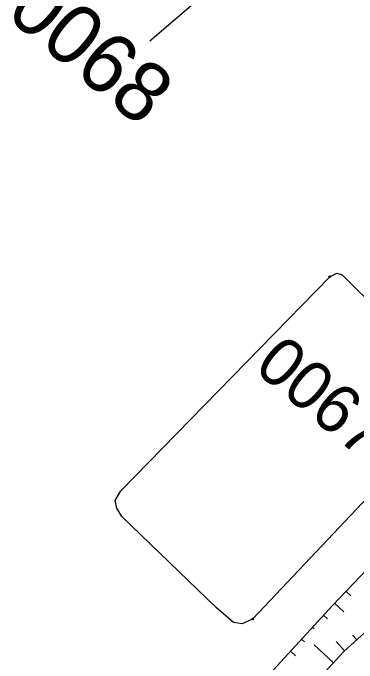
# Model space of a CAD drawing. Extents: x 344013 to 344423, y 298505 to 298795.
# Drawn here: x 344172.09 to 344193.18, y 298706.06 to 298745.94 of the extents above; entities that cross this region are included whole.
import ezdxf

# ---------------------------------------------------------------- set-up
doc = ezdxf.new("R2010")
doc.units = 0
for name, color, linetype in [('Default', 7, 'Continuous'), ('PS_CONST', 7, 'Continuous'), ('PS_SOLID', 7, 'Continuous'), ('TOPO_POINT', 7, 'Continuous'), ('TOPO_TALUS-TERRAIN NATUREL', 7, 'Continuous')]:
    doc.layers.add(name, color=color, linetype=linetype)

# ---------------------------------------------------------------- blocks, each defined once
blk = doc.blocks.new('POINT_DISPLAY')
at = {"layer": 'Default'}
blk.add_circle((0, 0), 0.05, dxfattribs=at)

msp = doc.modelspace()

# ---------------------------------------------------------------- linework, layer by layer
at = {"layer": 'PS_CONST'}
msp.add_line((344180.475, 298744.233), (344184.78, 298747.93), dxfattribs=at)
at = {"layer": 'PS_SOLID'}
msp.add_lwpolyline([(344186.775, 298708.762), (344186.137, 298708.472), (344185.611, 298708.543), (344184.558, 298709.458), (344178.763, 298715.051), (344178.45, 298715.571), (344178.356, 298716.027), (344178.695, 298716.632), (344191.505, 298729.761), (344191.946, 298729.981), (344192.26, 298729.87), (344199.324, 298722.877), (344199.449, 298722.421), (344199.394, 298722.145), (344198.827, 298721.518), (344186.775, 298708.762)], dxfattribs=at)
at = {"layer": 'TOPO_TALUS-TERRAIN NATUREL'}
for p, q in [((344192.496, 298710.462), (344192.791, 298710.179)), ((344191.803, 298709.741), (344192.363, 298709.202)), ((344191.126, 298709.004), (344191.372, 298708.781)), ((344190.453, 298708.264), (344190.558, 298708.168)), ((344193.163, 298707.478), (344192.892, 298707.78)), ((344189.78, 298707.524), (344189.96, 298707.36)), ((344192.419, 298706.81), (344191.904, 298707.383)), ((344191.737, 298706.078), (344190.544, 298707.176)), ((344189.105, 298706.786), (344189.411, 298706.505))]:
    msp.add_line(p, q, dxfattribs=at)
for points in [[(344185.518, 298702.89), (344189.41, 298707.116), (344191.688, 298709.622), (344193.823, 298711.844)], [(344193.64, 298707.907), (344192.371, 298706.767), (344190.985, 298705.261)]]:
    msp.add_lwpolyline(points, dxfattribs=at)

# ---------------------------------------------------------------- block references
at = {"layer": 'TOPO_POINT'}
for p in [(344191.505, 298729.761), (344186.775, 298708.762)]:
    msp.add_blockref('POINT_DISPLAY', p, dxfattribs=at)

# ---------------------------------------------------------------- texts
at = {"layer": 'PS_CONST'}
for s, height, p in [('0068', 3.662, (344171.524, 298745.815)), ('0067', 2.9662, (344186.769, 298724.069))]:
    msp.add_text(s, height=height, rotation=320.3665, dxfattribs=at).set_placement(p)

doc.saveas('drawing.dxf')
